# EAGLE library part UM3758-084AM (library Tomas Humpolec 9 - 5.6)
UM3758 - Tri-Stade Programmable Encoder/Decoder - Single-Chip CMOS construction - Operating voltage 3 - 12V
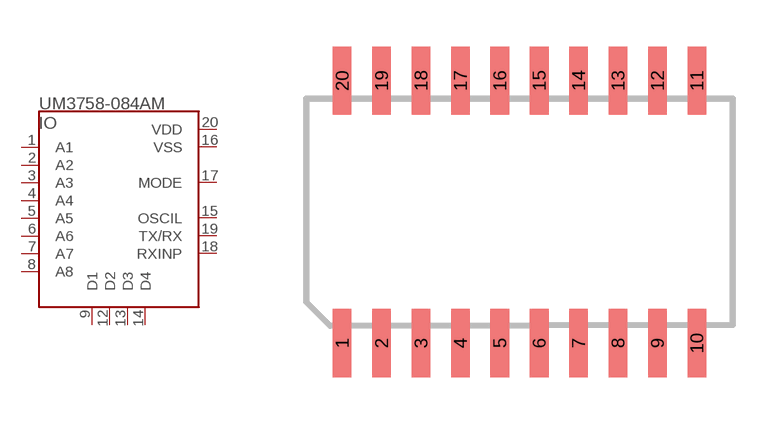
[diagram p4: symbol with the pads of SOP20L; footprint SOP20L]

Designator prefix IO

## UM3758-084AMSMD  [SOP20L]
1  A1  in
2  A2  in
3  A3  in
4  A4  in
5  A5  in
6  A6  in
7  A7  in
8  A8  in
9  D1
12  D2
13  D3
14  D4
15  OSCIL  oc
16  VSS  pwr
17  MODE  in
18  RXINP  in
19  TX/RX
20  VDD  pwr

## Footprint SOP20L (pad centres in mm)
SMD - SOP 20L Outline Dimensions
smd 0.6 x 2.2: 1 -5.08,-3.6; 2 -3.81,-3.6; 3 -2.54,-3.6; 4 -1.27,-3.6; 5 0,-3.6; 6 1.27,-3.6; 7 2.54,-3.6; 8 3.81,-3.6; 9 5.08,-3.6; 10 6.35,-3.6; 11 6.35,4.87; 12 5.08,4.87; 13 3.81,4.87; 14 2.54,4.87; 15 1.27,4.87; 16 0,4.87; 17 -1.27,4.87; 18 -2.54,4.87; 19 -3.81,4.87; 20 -5.08,4.87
